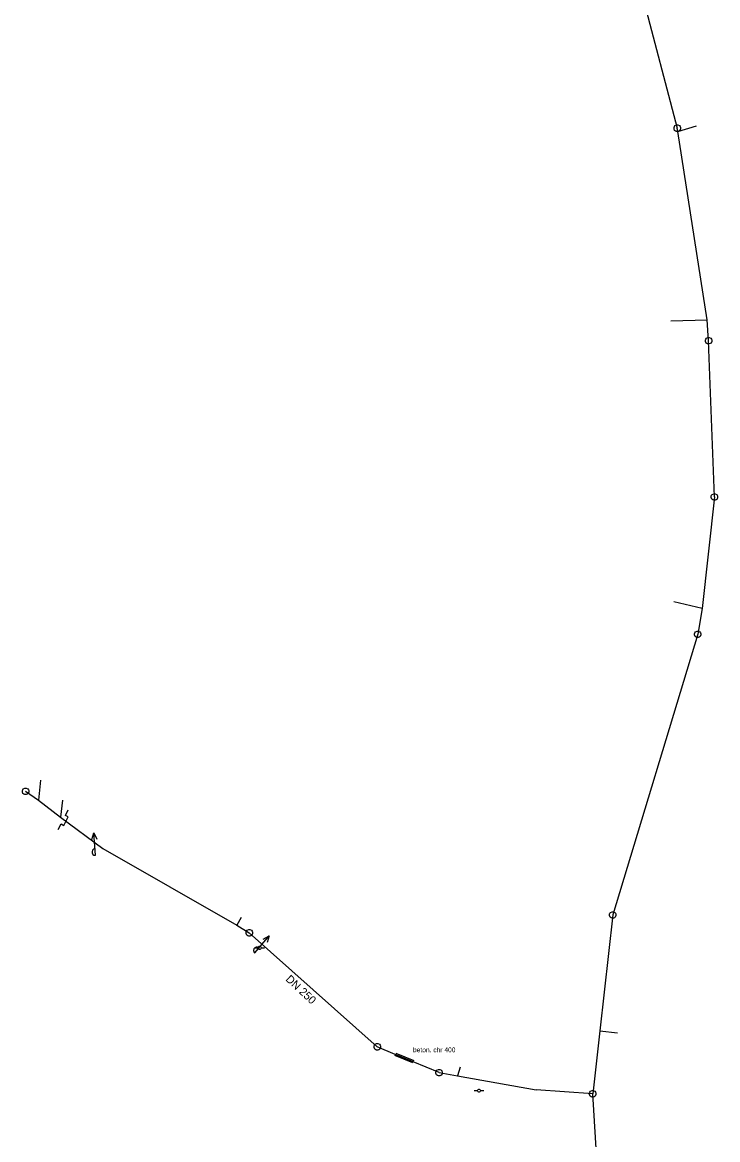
# Model space of a CAD drawing. Extents: x -717256 to -716843, y -1145423 to -1142840.
# Drawn here: x -717140.4 to -717031.8, y -1143188.5 to -1143014.1 of the extents above; entities that cross this region are included whole.
import ezdxf

# ---------------------------------------------------------------- set-up
doc = ezdxf.new("R2010")
doc.units = 0
for name, color, linetype in [('Vrstva 29', 7, 'Continuous'), ('Vrstva 30', 7, 'Continuous'), ('Vrstva 31', 7, 'Continuous'), ('Vrstva 9', 7, 'Continuous')]:
    doc.layers.add(name, color=color, linetype=linetype)

msp = doc.modelspace()

# ---------------------------------------------------------------- linework, layer by layer
at = {"layer": 'Vrstva 29'}
for p, q in [((-717082.088, -1143174.987), (-717079.281, -1143176.133)), ((-717079.432, -1143176.504), (-717082.239, -1143175.358))]:
    msp.add_line(p, q, dxfattribs=at)
at = {"layer": 'Vrstva 30'}
for p, q in [((-717047.501, -1142994.899), (-717038.15, -1143030.578)), ((-717038.6, -1143030.328), (-717038.5, -1143030.178)), ((-717038.5, -1143030.178), (-717038.25, -1143030.078)), ((-717038.25, -1143030.078), (-717038.05, -1143030.078)), ((-717038.05, -1143030.078), (-717037.8, -1143030.178)), ((-717037.8, -1143030.178), (-717037.7, -1143030.328)), ((-717038.65, -1143030.478), (-717038.6, -1143030.328)), ((-717038.65, -1143030.678), (-717038.65, -1143030.478)), ((-717038.55, -1143030.928), (-717038.65, -1143030.678)), ((-717038.4, -1143031.028), (-717038.55, -1143030.928)), ((-717038.25, -1143031.078), (-717038.4, -1143031.028)), ((-717038.05, -1143031.078), (-717038.25, -1143031.078)), ((-717038.053, -1143031.077), (-717038.15, -1143030.578)), ((-717033.482, -1143060.484), (-717038.053, -1143031.077)), ((-717037.9, -1143031.028), (-717038.05, -1143031.078)), ((-717037.75, -1143030.928), (-717037.9, -1143031.028)), ((-717037.65, -1143030.678), (-717037.75, -1143030.928)), ((-717037.7, -1143030.328), (-717037.65, -1143030.478)), ((-717037.65, -1143030.478), (-717037.65, -1143030.678)), ((-717033.254, -1143063.77), (-717033.482, -1143060.484)), ((-717033.704, -1143063.52), (-717033.604, -1143063.37)), ((-717033.604, -1143063.37), (-717033.354, -1143063.27)), ((-717033.354, -1143063.27), (-717033.154, -1143063.27)), ((-717033.154, -1143063.27), (-717032.904, -1143063.37)), ((-717032.904, -1143063.37), (-717032.804, -1143063.52)), ((-717033.754, -1143063.67), (-717033.704, -1143063.52)), ((-717033.754, -1143063.87), (-717033.754, -1143063.67)), ((-717033.654, -1143064.12), (-717033.754, -1143063.87)), ((-717033.504, -1143064.22), (-717033.654, -1143064.12)), ((-717033.354, -1143064.27), (-717033.504, -1143064.22)), ((-717033.154, -1143064.27), (-717033.354, -1143064.27)), ((-717032.342, -1143088.149), (-717033.254, -1143063.77)), ((-717033.004, -1143064.22), (-717033.154, -1143064.27)), ((-717032.854, -1143064.12), (-717033.004, -1143064.22)), ((-717032.754, -1143063.87), (-717032.854, -1143064.12)), ((-717032.804, -1143063.52), (-717032.754, -1143063.67)), ((-717032.754, -1143063.67), (-717032.754, -1143063.87)), ((-717032.792, -1143087.899), (-717032.692, -1143087.749)), ((-717032.692, -1143087.749), (-717032.442, -1143087.649)), ((-717032.442, -1143087.649), (-717032.242, -1143087.649)), ((-717032.242, -1143087.649), (-717031.992, -1143087.749)), ((-717031.992, -1143087.749), (-717031.892, -1143087.899)), ((-717032.342, -1143088.149), (-717034.273, -1143105.55)), ((-717032.842, -1143088.049), (-717032.792, -1143087.899)), ((-717032.842, -1143088.249), (-717032.842, -1143088.049)), ((-717032.742, -1143088.499), (-717032.842, -1143088.249)), ((-717032.592, -1143088.599), (-717032.742, -1143088.499)), ((-717032.442, -1143088.649), (-717032.592, -1143088.599)), ((-717032.242, -1143088.649), (-717032.442, -1143088.649)), ((-717032.092, -1143088.599), (-717032.242, -1143088.649)), ((-717031.942, -1143088.499), (-717032.092, -1143088.599)), ((-717031.842, -1143088.249), (-717031.942, -1143088.499)), ((-717031.892, -1143087.899), (-717031.842, -1143088.049)), ((-717031.842, -1143088.049), (-717031.842, -1143088.249)), ((-717034.273, -1143105.55), (-717034.959, -1143109.598)), ((-717034.959, -1143109.598), (-717048.212, -1143153.406)), ((-717035.459, -1143109.498), (-717035.409, -1143109.348)), ((-717035.459, -1143109.698), (-717035.459, -1143109.498)), ((-717035.359, -1143109.948), (-717035.459, -1143109.698)), ((-717035.409, -1143109.348), (-717035.309, -1143109.198)), ((-717035.209, -1143110.048), (-717035.359, -1143109.948)), ((-717035.309, -1143109.198), (-717035.059, -1143109.098)), ((-717035.059, -1143110.098), (-717035.209, -1143110.048)), ((-717035.059, -1143109.098), (-717034.859, -1143109.098)), ((-717034.859, -1143110.098), (-717035.059, -1143110.098)), ((-717034.859, -1143109.098), (-717034.609, -1143109.198)), ((-717034.709, -1143110.048), (-717034.859, -1143110.098)), ((-717034.559, -1143109.948), (-717034.709, -1143110.048)), ((-717034.609, -1143109.198), (-717034.509, -1143109.348)), ((-717034.459, -1143109.698), (-717034.559, -1143109.948)), ((-717034.509, -1143109.348), (-717034.459, -1143109.498)), ((-717034.459, -1143109.498), (-717034.459, -1143109.698)), ((-717140.352, -1143134.002), (-717140.302, -1143133.852)), ((-717140.352, -1143134.202), (-717140.352, -1143134.002)), ((-717140.252, -1143134.452), (-717140.352, -1143134.202)), ((-717140.302, -1143133.852), (-717140.202, -1143133.702)), ((-717140.102, -1143134.552), (-717140.252, -1143134.452)), ((-717140.202, -1143133.702), (-717139.952, -1143133.602)), ((-717139.952, -1143134.602), (-717140.102, -1143134.552)), ((-717139.952, -1143133.602), (-717139.752, -1143133.602)), ((-717139.752, -1143134.602), (-717139.952, -1143134.602)), ((-717139.852, -1143134.102), (-717137.835, -1143135.516)), ((-717139.752, -1143133.602), (-717139.502, -1143133.702)), ((-717139.602, -1143134.552), (-717139.752, -1143134.602)), ((-717139.452, -1143134.452), (-717139.602, -1143134.552)), ((-717139.502, -1143133.702), (-717139.402, -1143133.852)), ((-717139.352, -1143134.202), (-717139.452, -1143134.452)), ((-717139.402, -1143133.852), (-717139.352, -1143134.002)), ((-717139.352, -1143134.002), (-717139.352, -1143134.202)), ((-717137.835, -1143135.516), (-717134.412, -1143138.126)), ((-717134.412, -1143138.126), (-717127.779, -1143143.024)), ((-717127.779, -1143143.024), (-717106.899, -1143154.987)), ((-717048.212, -1143153.406), (-717050.243, -1143171.518)), ((-717048.712, -1143153.306), (-717048.662, -1143153.156)), ((-717048.712, -1143153.506), (-717048.712, -1143153.306)), ((-717048.612, -1143153.756), (-717048.712, -1143153.506)), ((-717048.662, -1143153.156), (-717048.562, -1143153.006)), ((-717048.462, -1143153.856), (-717048.612, -1143153.756)), ((-717048.562, -1143153.006), (-717048.312, -1143152.906)), ((-717048.312, -1143153.906), (-717048.462, -1143153.856)), ((-717048.312, -1143152.906), (-717048.112, -1143152.906)), ((-717048.112, -1143153.906), (-717048.312, -1143153.906)), ((-717048.112, -1143152.906), (-717047.862, -1143153.006)), ((-717047.962, -1143153.856), (-717048.112, -1143153.906)), ((-717047.812, -1143153.756), (-717047.962, -1143153.856)), ((-717047.862, -1143153.006), (-717047.762, -1143153.156)), ((-717047.712, -1143153.506), (-717047.812, -1143153.756)), ((-717047.762, -1143153.156), (-717047.712, -1143153.306)), ((-717047.712, -1143153.306), (-717047.712, -1143153.506)), ((-717106.899, -1143154.987), (-717104.932, -1143156.204)), ((-717105.382, -1143155.954), (-717105.282, -1143155.804)), ((-717105.282, -1143155.804), (-717105.032, -1143155.704)), ((-717105.032, -1143155.704), (-717104.832, -1143155.704)), ((-717104.832, -1143155.704), (-717104.582, -1143155.804)), ((-717104.582, -1143155.804), (-717104.482, -1143155.954)), ((-717105.432, -1143156.104), (-717105.382, -1143155.954)), ((-717105.432, -1143156.304), (-717105.432, -1143156.104)), ((-717105.332, -1143156.554), (-717105.432, -1143156.304)), ((-717105.182, -1143156.654), (-717105.332, -1143156.554)), ((-717105.032, -1143156.704), (-717105.182, -1143156.654)), ((-717104.832, -1143156.704), (-717105.032, -1143156.704)), ((-717104.932, -1143156.204), (-717084.96, -1143174.003)), ((-717104.682, -1143156.654), (-717104.832, -1143156.704)), ((-717104.532, -1143156.554), (-717104.682, -1143156.654)), ((-717104.432, -1143156.304), (-717104.532, -1143156.554)), ((-717104.482, -1143155.954), (-717104.432, -1143156.104)), ((-717104.432, -1143156.104), (-717104.432, -1143156.304)), ((-717050.243, -1143171.518), (-717051.345, -1143181.336)), ((-717085.46, -1143173.903), (-717085.41, -1143173.753)), ((-717085.46, -1143174.103), (-717085.46, -1143173.903)), ((-717085.36, -1143174.353), (-717085.46, -1143174.103)), ((-717085.41, -1143173.753), (-717085.31, -1143173.603)), ((-717085.21, -1143174.453), (-717085.36, -1143174.353)), ((-717085.31, -1143173.603), (-717085.06, -1143173.503)), ((-717085.06, -1143174.503), (-717085.21, -1143174.453)), ((-717085.06, -1143173.503), (-717084.86, -1143173.503)), ((-717084.86, -1143174.503), (-717085.06, -1143174.503)), ((-717082.164, -1143175.173), (-717084.96, -1143174.003)), ((-717084.86, -1143173.503), (-717084.61, -1143173.603)), ((-717084.71, -1143174.453), (-717084.86, -1143174.503)), ((-717084.56, -1143174.353), (-717084.71, -1143174.453)), ((-717084.61, -1143173.603), (-717084.51, -1143173.753)), ((-717084.46, -1143174.103), (-717084.56, -1143174.353)), ((-717084.51, -1143173.753), (-717084.46, -1143173.903)), ((-717084.46, -1143173.903), (-717084.46, -1143174.103)), ((-717079.357, -1143176.319), (-717082.164, -1143175.173)), ((-717075.311, -1143178.029), (-717079.357, -1143176.319)), ((-717075.811, -1143177.929), (-717075.761, -1143177.779)), ((-717075.811, -1143178.129), (-717075.811, -1143177.929)), ((-717075.711, -1143178.379), (-717075.811, -1143178.129)), ((-717075.761, -1143177.779), (-717075.661, -1143177.629)), ((-717075.561, -1143178.479), (-717075.711, -1143178.379)), ((-717075.661, -1143177.629), (-717075.411, -1143177.529)), ((-717075.411, -1143178.529), (-717075.561, -1143178.479)), ((-717075.411, -1143177.529), (-717075.211, -1143177.529)), ((-717075.211, -1143178.529), (-717075.411, -1143178.529)), ((-717075.311, -1143178.029), (-717072.448, -1143178.534)), ((-717075.211, -1143177.529), (-717074.961, -1143177.629)), ((-717075.061, -1143178.479), (-717075.211, -1143178.529)), ((-717074.911, -1143178.379), (-717075.061, -1143178.479)), ((-717074.961, -1143177.629), (-717074.861, -1143177.779)), ((-717074.811, -1143178.129), (-717074.911, -1143178.379)), ((-717074.861, -1143177.779), (-717074.811, -1143177.929)), ((-717074.811, -1143177.929), (-717074.811, -1143178.129)), ((-717072.448, -1143178.534), (-717060.171, -1143180.703)), ((-717051.345, -1143181.336), (-717060.171, -1143180.703)), ((-717051.845, -1143181.236), (-717051.795, -1143181.086)), ((-717051.845, -1143181.436), (-717051.845, -1143181.236)), ((-717051.745, -1143181.686), (-717051.845, -1143181.436)), ((-717051.795, -1143181.086), (-717051.695, -1143180.936)), ((-717051.595, -1143181.786), (-717051.745, -1143181.686)), ((-717051.695, -1143180.936), (-717051.445, -1143180.836)), ((-717051.445, -1143181.836), (-717051.595, -1143181.786)), ((-717051.445, -1143180.836), (-717051.245, -1143180.836)), ((-717051.245, -1143181.836), (-717051.445, -1143181.836)), ((-717049.52, -1143210.751), (-717051.345, -1143181.336)), ((-717051.245, -1143180.836), (-717050.995, -1143180.936)), ((-717051.095, -1143181.786), (-717051.245, -1143181.836)), ((-717050.945, -1143181.686), (-717051.095, -1143181.786)), ((-717050.995, -1143180.936), (-717050.895, -1143181.086)), ((-717050.845, -1143181.436), (-717050.945, -1143181.686)), ((-717050.895, -1143181.086), (-717050.845, -1143181.236)), ((-717050.845, -1143181.236), (-717050.845, -1143181.436))]:
    msp.add_line(p, q, dxfattribs=at)
at = {"layer": 'Vrstva 31'}
for p, q in [((-717038.053, -1143031.077), (-717035.152, -1143030.208)), ((-717039.158, -1143060.681), (-717033.482, -1143060.484)), ((-717034.273, -1143105.55), (-717038.693, -1143104.532)), ((-717137.542, -1143132.389), (-717137.835, -1143135.516)), ((-717134.093, -1143135.475), (-717134.412, -1143138.126)), ((-717106.181, -1143153.825), (-717106.899, -1143154.987)), ((-717050.243, -1143171.518), (-717047.472, -1143171.793)), ((-717072.037, -1143177.192), (-717072.448, -1143178.534))]:
    msp.add_line(p, q, dxfattribs=at)
at = {"layer": 'Vrstva 9'}
for p, q in [((-717133.873, -1143139.432), (-717133.193, -1143138.095)), ((-717133.638, -1143137.868), (-717133.184, -1143136.977)), ((-717133.193, -1143138.095), (-717133.638, -1143137.868)), ((-717134.773, -1143140.096), (-717134.319, -1143139.205)), ((-717134.319, -1143139.205), (-717133.873, -1143139.432)), ((-717129.522, -1143141.631), (-717129.202, -1143140.603)), ((-717128.927, -1143144.092), (-717129.202, -1143140.603)), ((-717129.202, -1143140.603), (-717128.725, -1143141.568)), ((-717129.393, -1143143.276), (-717129.473, -1143143.533)), ((-717129.473, -1143143.533), (-717129.457, -1143143.733)), ((-717129.251, -1143143.165), (-717129.393, -1143143.276)), ((-717129.105, -1143143.103), (-717129.251, -1143143.165)), ((-717129.006, -1143143.095), (-717129.105, -1143143.103)), ((-717129.457, -1143143.733), (-717129.338, -1143143.974)), ((-717129.338, -1143143.974), (-717129.18, -1143144.062)), ((-717129.18, -1143144.062), (-717129.027, -1143144.1)), ((-717129.027, -1143144.1), (-717128.927, -1143144.092)), ((-717104.089, -1143159.334), (-717101.816, -1143156.673)), ((-717102.77, -1143157.173), (-717101.816, -1143156.673)), ((-717101.816, -1143156.673), (-717102.161, -1143157.693)), ((-717104.209, -1143158.705), (-717104.296, -1143158.96)), ((-717104.296, -1143158.96), (-717104.247, -1143159.134)), ((-717104.247, -1143159.134), (-717104.165, -1143159.269)), ((-717104.08, -1143158.553), (-717104.209, -1143158.705)), ((-717104.165, -1143159.269), (-717104.089, -1143159.334)), ((-717103.841, -1143158.428), (-717104.08, -1143158.553)), ((-717104.072, -1143158.538), (-717103.572, -1143158.538)), ((-717103.662, -1143158.449), (-717103.841, -1143158.428)), ((-717103.516, -1143158.509), (-717103.662, -1143158.449)), ((-717103.572, -1143158.488), (-717103.522, -1143158.388)), ((-717103.572, -1143158.588), (-717103.572, -1143158.488)), ((-717103.522, -1143158.688), (-717103.572, -1143158.588)), ((-717103.522, -1143158.388), (-717103.472, -1143158.338)), ((-717103.472, -1143158.738), (-717103.522, -1143158.688)), ((-717103.44, -1143158.574), (-717103.516, -1143158.509)), ((-717103.472, -1143158.338), (-717103.372, -1143158.288)), ((-717103.372, -1143158.788), (-717103.472, -1143158.738)), ((-717103.372, -1143158.288), (-717103.272, -1143158.288)), ((-717103.272, -1143158.788), (-717103.372, -1143158.788)), ((-717103.272, -1143158.288), (-717103.172, -1143158.338)), ((-717103.172, -1143158.738), (-717103.272, -1143158.788)), ((-717103.172, -1143158.338), (-717103.122, -1143158.388)), ((-717103.122, -1143158.688), (-717103.172, -1143158.738)), ((-717103.122, -1143158.388), (-717103.072, -1143158.488)), ((-717103.072, -1143158.588), (-717103.122, -1143158.688)), ((-717103.072, -1143158.488), (-717103.072, -1143158.588)), ((-717103.072, -1143158.538), (-717102.572, -1143158.538)), ((-717069.835, -1143180.843), (-717069.335, -1143180.843)), ((-717069.335, -1143180.793), (-717069.285, -1143180.693)), ((-717069.335, -1143180.893), (-717069.335, -1143180.793)), ((-717069.285, -1143180.993), (-717069.335, -1143180.893)), ((-717069.285, -1143180.693), (-717069.235, -1143180.643)), ((-717069.235, -1143181.043), (-717069.285, -1143180.993)), ((-717069.235, -1143180.643), (-717069.135, -1143180.593)), ((-717069.135, -1143181.093), (-717069.235, -1143181.043)), ((-717069.135, -1143180.593), (-717069.035, -1143180.593)), ((-717069.035, -1143181.093), (-717069.135, -1143181.093)), ((-717069.035, -1143180.593), (-717068.935, -1143180.643)), ((-717068.935, -1143181.043), (-717069.035, -1143181.093)), ((-717068.935, -1143180.643), (-717068.885, -1143180.693)), ((-717068.885, -1143180.993), (-717068.935, -1143181.043)), ((-717068.885, -1143180.693), (-717068.835, -1143180.793)), ((-717068.835, -1143180.893), (-717068.885, -1143180.993)), ((-717068.835, -1143180.793), (-717068.835, -1143180.893)), ((-717068.835, -1143180.843), (-717068.335, -1143180.843))]:
    msp.add_line(p, q, dxfattribs=at)

# ---------------------------------------------------------------- texts
at = {"layer": 'Vrstva 30'}
msp.add_text('DN 250', height=1.25, rotation=316.8, dxfattribs=at).set_placement((-717099.362, -1143163.566))
msp.add_text('beton. chr 400', height=0.74999, dxfattribs=at).set_placement((-717079.385, -1143174.845))

doc.saveas('drawing.dxf')
